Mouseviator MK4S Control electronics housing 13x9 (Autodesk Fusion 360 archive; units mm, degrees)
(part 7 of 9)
sketch "Sketch1" plane through (0, 0, 5) normal (0, 0, 1) x axis (-1, 0, 0)
  line L1 (-98.9644, -53.9879) -> (-98.9644, -59.9879)
  line L2 (-92.9644, -53.9879) -> (-98.9644, -53.9879)
  line L3 (-92.9644, -59.9879) -> (-92.9644, -53.9879)
  line L4 (-98.9644, -59.9879) -> (-92.9644, -59.9879)
  line L5 (-12.9644, 60.0121) -> (-12.9644, 66.0121)
  line L6 (-18.9644, 60.0121) -> (-12.9644, 60.0121)
  line L7 (-18.9644, 66.0121) -> (-18.9644, 60.0121)
  line L8 (-12.9644, 66.0121) -> (-18.9644, 66.0121)
  line L9 (-45.9644, -51.9879) -> (-20.9644, -51.9879)
  line L10 (-40.9644, -54.9879) -> (-45.9644, -51.9879)
  line L11 (-70.9644, -54.9879) -> (-40.9644, -54.9879)
  line L12 (-65.9644, -51.9879) -> (-70.9644, -54.9879)
  line L13 (-90.9644, -51.9879) -> (-65.9644, -51.9879)
  line L14 (-90.9644, -6.9879) -> (-90.9644, -51.9879)
  line L15 (-93.9644, -11.9879) -> (-90.9644, -6.9879)
  line L16 (-93.9644, 18.0121) -> (-93.9644, -11.9879)
  line L17 (-90.9644, 13.0121) -> (-93.9644, 18.0121)
  line L18 (-90.9644, 58.0121) -> (-90.9644, 13.0121)
  line L19 (-65.9644, 58.0121) -> (-90.9644, 58.0121)
  line L20 (-70.9644, 61.0121) -> (-65.9644, 58.0121)
  line L21 (-40.9644, 61.0121) -> (-70.9644, 61.0121)
  line L22 (-45.9644, 58.0121) -> (-40.9644, 61.0121)
  line L23 (-20.9644, 58.0121) -> (-45.9644, 58.0121)
  line L24 (-20.9644, 13.0121) -> (-20.9644, 58.0121)
  line L25 (-17.9644, 18.0121) -> (-20.9644, 13.0121)
  line L26 (-17.9644, -11.9879) -> (-17.9644, 18.0121)
  line L27 (-20.9644, -6.9879) -> (-17.9644, -11.9879)
  line L28 (-20.9644, -51.9879) -> (-20.9644, -6.9879)
  line L29 (-12.9644, -53.9879) -> (-18.9644, -53.9879)
  line L30 (-12.9644, -59.9879) -> (-12.9644, -53.9879)
  line L31 (-18.9644, -59.9879) -> (-12.9644, -59.9879)
  line L32 (-18.9644, -53.9879) -> (-18.9644, -59.9879)
  line L33 (-98.9644, 60.0121) -> (-92.9644, 60.0121)
  line L34 (-98.9644, 66.0121) -> (-98.9644, 60.0121)
  line L35 (-92.9644, 66.0121) -> (-98.9644, 66.0121)
  line L36 (-92.9644, 60.0121) -> (-92.9644, 66.0121)
  line L37 (-10.9644, -6.9879) -> (-10.9644, -61.9879)
  line L38 (-13.9644, -11.9879) -> (-10.9644, -6.9879)
  line L39 (-13.9644, 18.0121) -> (-13.9644, -11.9879)
  line L40 (-10.9644, 13.0121) -> (-13.9644, 18.0121)
  line L41 (-10.9644, 68.0121) -> (-10.9644, 13.0121)
  line L42 (-45.9644, 68.0121) -> (-10.9644, 68.0121)
  line L43 (-40.9644, 65.0121) -> (-45.9644, 68.0121)
  line L44 (-70.9644, 65.0121) -> (-40.9644, 65.0121)
  line L45 (-65.9644, 68.0121) -> (-70.9644, 65.0121)
  line L46 (-100.9644, 68.0121) -> (-65.9644, 68.0121)
  line L47 (-100.9644, 13.0121) -> (-100.9644, 68.0121)
  line L48 (-97.9644, 18.0121) -> (-100.9644, 13.0121)
  line L49 (-97.9644, -11.9879) -> (-97.9644, 18.0121)
  line L50 (-100.9644, -6.9879) -> (-97.9644, -11.9879)
  line L51 (-100.9644, -61.9879) -> (-100.9644, -6.9879)
  line L52 (-65.9644, -61.9879) -> (-100.9644, -61.9879)
  line L53 (-70.9644, -58.9879) -> (-65.9644, -61.9879)
  line L54 (-40.9644, -58.9879) -> (-70.9644, -58.9879)
  line L55 (-45.9644, -61.9879) -> (-40.9644, -58.9879)
  line L56 (-10.9644, -61.9879) -> (-45.9644, -61.9879)
  line L57 (-100.9644, -61.9879) -> (-10.9644, -61.9879)
  line L58 (-99.9644, -60.9879) -> (-100.9644, -61.9879)
  line L59 (-91.9644, -60.9879) -> (-99.9644, -60.9879)
  line L60 (-91.9644, -59.9879) -> (-91.9644, -60.9879)
  line L61 (-19.9644, -59.9879) -> (-91.9644, -59.9879)
  line L62 (-19.9644, -60.9879) -> (-19.9644, -59.9879)
  line L63 (-11.9644, -60.9879) -> (-19.9644, -60.9879)
  line L64 (-10.9644, -61.9879) -> (-11.9644, -60.9879)
  line L65 (-99.9437, -61.0379) -> (-100.8937, -61.9879)
  line L66 (-91.9144, -61.0379) -> (-99.9437, -61.0379)
  line L67 (-91.9144, -60.0379) -> (-91.9144, -61.0379)
  line L68 (-20.0144, -60.0379) -> (-91.9144, -60.0379)
  line L69 (-20.0144, -61.0379) -> (-20.0144, -60.0379)
  line L70 (-11.9851, -61.0379) -> (-20.0144, -61.0379)
  line L71 (-11.0351, -61.9879) -> (-11.9851, -61.0379)
  circle C1 centre (-24.4644, 61.5121) radius 1.7
  circle C2 centre (-93.9644, 54.5121) radius 1.7
  circle C3 centre (-87.4644, -55.4879) radius 1.7
  circle C4 centre (-17.4644, -48.4879) radius 1.7
  circle C5 centre (-24.4644, -55.4879) radius 1.7
  circle C6 centre (-93.9644, -48.4879) radius 1.7
  circle C7 centre (-87.4644, 61.5121) radius 1.7
  circle C8 centre (-17.4644, 54.5121) radius 1.7
  point P46 (-10.9644, -61.9879)
  point P74 (-10.9644, -61.9879)
  point P61 (-100.9644, -61.9879)
  point P76 (-100.9644, -61.9879)
  point P68 (-99.9644, -60.9879)
  point P77 (-99.9644, -60.9879)
  point P69 (-91.9644, -60.9879)
  point P78 (-91.9644, -60.9879)
  point P70 (-91.9644, -59.9879)
  point P79 (-91.9644, -59.9879)
  point P71 (-19.9644, -59.9879)
  point P80 (-19.9644, -59.9879)
  point P72 (-19.9644, -60.9879)
  point P81 (-19.9644, -60.9879)
  point P73 (-11.9644, -60.9879)
  point P82 (-11.9644, -60.9879)
  point P89 (-11.0351, -61.9879)
  point P90 (-100.8937, -61.9879)
  point P75 (-100.9644, -61.9879)
  coincident P46 P74
  coincident P61 P76
  coincident P68 P77
  coincident P69 P78
  coincident P70 P79
  coincident P71 P80
  coincident P72 P81
  coincident P73 P82
  coincident L56 P89
  coincident L52 P90
  dimension "d228_3_3" distance L57 L70 = 0.95 (= "side_wall_thick1")
  dimension "d229_3_3" distance L57 L68 = 1.95 (= "side_wall_thick2")
  dimension "d230_3_3" distance L57 L66 = 0.95 (= "side_wall_thick1")
  dimension "d231_3_3" distance P74 P75 = 90 (= "plate_height")
  dimension "d232_3_3" distance L64 L71 = 0.05 (= "wall_clearance")
  dimension "d233_3_3" distance L58 L65 = 0.05 (= "wall_clearance")
  dimension "d234_3_3" angle L57 L58 = 45 (= "wall_rorner_angle")
  dimension "d235_3_3" distance P74 L69 = 9.05 (= "side_wall_col_length")
  dimension "d244_3_3" distance P75 L67 = 9.05 (= "side_wall_col_length")
extrude "Extrude1" new body sketch "Sketch1" profile of L52 L53 L55 L56 blind 69.9 (= "column_height - ( 2 * wall_clearance )") named "d217_3_3" from offset 0.05 (= "wall_clearance") named "d216_3_3"
sketch "Sketch2" plane through (0, 61.9879, 0) normal (0, 1, 0) x axis (-1, 0, 0)
  line L1 (-11.0351, 74.95) -> (-100.8937, 74.95)
  line L2 (-100.8937, 74.95) -> (-100.8937, 5.05)
  line L3 (-11.0351, 74.95) -> (-11.0351, 5.05)
  line L4 (-11.0351, 5.05) -> (-100.8937, 5.05)
  line L5 (-11.0351, 74.95) -> (-11.0351, 5.05)
  line L6 (-100.8937, 74.95) -> (-11.0351, 74.95)
  line L7 (-100.8937, 5.05) -> (-100.8937, 74.95)
  line L8 (-90.8937, 64.95) -> (-21.0351, 64.95)
  line L9 (-90.8937, 15.05) -> (-90.8937, 64.95)
  line L10 (-21.0351, 15.05) -> (-90.8937, 15.05)
  line L11 (-21.0351, 64.95) -> (-21.0351, 15.05)
  circle C1 centre (-95.9644, 60) radius 1.7
  circle C2 centre (-95.9644, 20) radius 1.7
  circle C3 centre (-15.9644, 20) radius 1.7
  circle C4 centre (-15.9644, 60) radius 1.7
hole "Hole1" HoleDepth 4 named "d220_3_3" HoleDiameter 3.4 named "d221_3_3" TipAngle 118 named "d222_3_3"
sketch "Sketch3" plane through (0, 61.9879, 0) normal (0, 1, 0) x axis (-1, 0, 0)
  line L1 (-11.0351, 5.05) -> (-100.8937, 5.05)
  line L2 (-11.0351, 74.95) -> (-11.0351, 5.05)
  line L3 (-100.8937, 74.95) -> (-11.0351, 74.95)
  line L4 (-100.8937, 5.05) -> (-100.8937, 74.95)
  line L5 (-55.9644, -6.6527) -> (-55.9644, 156.5527)
  line L6 (83.5909, 40) -> (-105.6612, 40)
  line L7 (-100.8937, 64.95) -> (-100.8937, 74.95)
  line L8 (-94.8937, 74.95) -> (-100.8937, 74.95)
  line L9 (-94.8937, 59.95) -> (-94.8937, 74.95)
  line L10 (-100.8937, 64.95) -> (-94.8937, 59.95)
  line L11 (-100.9437, 64.9735) -> (-106.8437, 60)
  line L12 (-106.8437, 60) -> (-106.8437, 74.9)
  line L13 (-100.8937, 64.9735) -> (-100.9437, 64.9735)
  line L14 (-100.8937, 74.9) -> (-106.8437, 74.9)
  line L15 (-100.8937, 5.1) -> (-106.8437, 5.1)
  line L16 (-106.8437, 20) -> (-106.8437, 5.1)
  line L17 (-100.9437, 15.0265) -> (-106.8437, 20)
  line L18 (-100.8937, 15.0265) -> (-100.9437, 15.0265)
  line L19 (-100.8937, 15.05) -> (-100.8937, 5.05)
  line L20 (-94.8937, 5.05) -> (-100.8937, 5.05)
  line L21 (-94.8937, 20.05) -> (-94.8937, 5.05)
  line L22 (-100.8937, 15.05) -> (-94.8937, 20.05)
  line L23 (-11.0351, 5.1) -> (-5.0851, 5.1)
  line L24 (-5.0851, 20) -> (-5.0851, 5.1)
  line L25 (-10.9851, 15.0265) -> (-5.0851, 20)
  line L26 (-11.0351, 15.0265) -> (-10.9851, 15.0265)
  line L27 (-11.0351, 15.05) -> (-11.0351, 5.05)
  line L28 (-17.0351, 5.05) -> (-11.0351, 5.05)
  line L29 (-17.0351, 20.05) -> (-17.0351, 5.05)
  line L30 (-11.0351, 15.05) -> (-17.0351, 20.05)
  line L31 (-11.0351, 74.9) -> (-5.0851, 74.9)
  line L32 (-5.0851, 60) -> (-5.0851, 74.9)
  line L33 (-11.0351, 64.9735) -> (-10.9851, 64.9735)
  line L34 (-10.9851, 64.9735) -> (-5.0851, 60)
  line L35 (-11.0351, 64.95) -> (-11.0351, 74.95)
  line L36 (-17.0351, 74.95) -> (-11.0351, 74.95)
  line L37 (-17.0351, 59.95) -> (-17.0351, 74.95)
  line L38 (-11.0351, 64.95) -> (-17.0351, 59.95)
  point P17 (-100.8937, 64.9735)
  point P18 (-100.8937, 74.9)
  point P10 (-100.8937, 74.95)
  point P24 (-100.8937, 5.05)
  point P11 (-100.8937, 64.95)
  point P25 (-100.8937, 15.05)
  point P12 (-94.8937, 74.95)
  point P26 (-94.8937, 5.05)
  point P13 (-94.8937, 59.95)
  point P27 (-94.8937, 20.05)
  point P14 (-100.9437, 64.9735)
  point P22 (-100.9437, 15.0265)
  point P15 (-106.8437, 60)
  point P21 (-106.8437, 20)
  point P16 (-106.8437, 74.9)
  point P19 (-106.8437, 5.1)
  point P23 (-100.8937, 15.0265)
  point P20 (-100.8937, 5.1)
  point P42 (-11.0351, 74.95)
  point P43 (-11.0351, 64.95)
  point P44 (-17.0351, 74.95)
  point P45 (-17.0351, 59.95)
  point P40 (-10.9851, 64.9735)
  point P39 (-5.0851, 60)
  point P37 (-5.0851, 74.9)
  point P41 (-11.0351, 64.9735)
  point P38 (-11.0351, 74.9)
  point P28 (-5.0851, 5.1)
  point P29 (-11.0351, 5.1)
  point P30 (-5.0851, 20)
  point P31 (-10.9851, 15.0265)
  point P32 (-11.0351, 15.0265)
  point P33 (-11.0351, 5.05)
  point P34 (-11.0351, 15.05)
  point P35 (-17.0351, 5.05)
  point P36 (-17.0351, 20.05)
  vertical L5
  horizontal L6
  midpoint L3 L5
  midpoint L2 L6
  coincident L7 P17
  coincident L4 P17
  perpendicular L7 L14
  coincident L4 P18
  symmetric L6 P10 P24
  symmetric L6 P11 P25
  symmetric L6 P12 P26
  symmetric L6 P13 P27
  symmetric L6 P14 P22
  symmetric L6 P15 P21
  symmetric L6 P16 P19
  symmetric L6 P17 P23
  symmetric L6 P18 P20
  symmetric L5 P10 P42
  symmetric L5 P11 P43
  symmetric L5 P12 P44
  symmetric L5 P13 P45
  symmetric L5 P14 P40
  symmetric L5 P15 P39
  symmetric L5 P16 P37
  symmetric L5 P17 P41
  symmetric L5 P18 P38
  symmetric L5 P19 P28
  symmetric L5 P20 P29
  symmetric L5 P21 P30
  symmetric L5 P22 P31
  symmetric L5 P23 P32
  symmetric L5 P24 P33
  symmetric L5 P25 P34
  symmetric L5 P26 P35
  symmetric L5 P27 P36
  dimension "d332_3_3" distance P12 P13 = 15 (= "join_width2")
  dimension "d333_3_3" distance P10 P12 = 6 (= "join_depth * 2")
  dimension "d334_3_3" distance P10 P11 = 10 (= "join_width1")
  dimension "d336_3_3" distance P15 P16 = 14.9 (= "join_width2 - ( 2 * wall_clearance )")
  dimension "d337_3_3" distance P16 P18 = 5.95 (= "join_depth * 2 - wall_clearance")
  dimension "d338_3_3" distance P14 P17 = 0.05 (= "wall_clearance")
position "Position26"
extrude "Extrude3" add sketch "Sketch3" profile of L1 L3 L4 L7 L8 L9 L10 L12 L11 L13 L14 L15 L16 L17 L18 L19 L20 L21 L22 against normal blind 0.95 named "d343_2" (magnitude of "-side_wall_thick1")
sketch "Sketch4" plane through (0, 61.9879, 0) normal (0, 1, 0) x axis (1, 0, 0)
  line L1 (11.0351, -5.05) -> (100.8937, -5.05)
  line L2 (11.0351, -74.95) -> (11.0351, -5.05)
  line L3 (100.8937, -74.95) -> (11.0351, -74.95)
  line L4 (100.8937, -5.05) -> (100.8937, -74.95)
  line L5 (36.6374, -5.05) -> (36.6374, -12.415)
  line L6 (26.6374, -5.05) -> (26.6374, -12.415)
  circle C1 centre (15.9644, -20) radius 1.7
  circle C2 centre (95.9644, -60) radius 1.7
  circle C3 centre (95.9644, -20) radius 1.7
  circle C4 centre (15.9644, -60) radius 1.7
  arc A1 centre (31.6374, -12.415) radius 5 clockwise from (36.6374, -12.415) to (26.6374, -12.415)
  point P12 (36.6374, -5.05)
  point P14 (26.6374, -5.05)
  coincident L1 P12
  tangent L5 A1
  coincident L1 P14
  tangent L6 A1
  perpendicular L1 L6
  dimension "cable_hole_d_3" diameter A1 = 10
extrude "Extrude4" cut sketch "Sketch4" profile of A1 L1 L5 L6 against normal blind 2 named "d517_1"
sketch "Sketch1" plane through (0, 0, 5) normal (0, 0, 1) x axis (-1, 0, 0)
  line L1 (-98.9644, -53.9879) -> (-98.9644, -59.9879)
  line L2 (-92.9644, -53.9879) -> (-98.9644, -53.9879)
  line L3 (-92.9644, -59.9879) -> (-92.9644, -53.9879)
  line L4 (-98.9644, -59.9879) -> (-92.9644, -59.9879)
  line L5 (-12.9644, 60.0121) -> (-12.9644, 66.0121)
  line L6 (-18.9644, 60.0121) -> (-12.9644, 60.0121)
  line L7 (-18.9644, 66.0121) -> (-18.9644, 60.0121)
  line L8 (-12.9644, 66.0121) -> (-18.9644, 66.0121)
  line L9 (-45.9644, -51.9879) -> (-20.9644, -51.9879)
  line L10 (-40.9644, -54.9879) -> (-45.9644, -51.9879)
  line L11 (-70.9644, -54.9879) -> (-40.9644, -54.9879)
  line L12 (-65.9644, -51.9879) -> (-70.9644, -54.9879)
  line L13 (-90.9644, -51.9879) -> (-65.9644, -51.9879)
  line L14 (-90.9644, -6.9879) -> (-90.9644, -51.9879)
  line L15 (-93.9644, -11.9879) -> (-90.9644, -6.9879)
  line L16 (-93.9644, 18.0121) -> (-93.9644, -11.9879)
  line L17 (-90.9644, 13.0121) -> (-93.9644, 18.0121)
  line L18 (-90.9644, 58.0121) -> (-90.9644, 13.0121)
  line L19 (-65.9644, 58.0121) -> (-90.9644, 58.0121)
  line L20 (-70.9644, 61.0121) -> (-65.9644, 58.0121)
  line L21 (-40.9644, 61.0121) -> (-70.9644, 61.0121)
  line L22 (-45.9644, 58.0121) -> (-40.9644, 61.0121)
  line L23 (-20.9644, 58.0121) -> (-45.9644, 58.0121)
  line L24 (-20.9644, 13.0121) -> (-20.9644, 58.0121)
  line L25 (-17.9644, 18.0121) -> (-20.9644, 13.0121)
  line L26 (-17.9644, -11.9879) -> (-17.9644, 18.0121)
  line L27 (-20.9644, -6.9879) -> (-17.9644, -11.9879)
  line L28 (-20.9644, -51.9879) -> (-20.9644, -6.9879)
  line L29 (-12.9644, -53.9879) -> (-18.9644, -53.9879)
  line L30 (-12.9644, -59.9879) -> (-12.9644, -53.9879)
  line L31 (-18.9644, -59.9879) -> (-12.9644, -59.9879)
  line L32 (-18.9644, -53.9879) -> (-18.9644, -59.9879)
  line L33 (-98.9644, 60.0121) -> (-92.9644, 60.0121)
  line L34 (-98.9644, 66.0121) -> (-98.9644, 60.0121)
  line L35 (-92.9644, 66.0121) -> (-98.9644, 66.0121)
  line L36 (-92.9644, 60.0121) -> (-92.9644, 66.0121)
  line L37 (-10.9644, -6.9879) -> (-10.9644, -61.9879)
  line L38 (-13.9644, -11.9879) -> (-10.9644, -6.9879)
  line L39 (-13.9644, 18.0121) -> (-13.9644, -11.9879)
  line L40 (-10.9644, 13.0121) -> (-13.9644, 18.0121)
  line L41 (-10.9644, 68.0121) -> (-10.9644, 13.0121)
  line L42 (-45.9644, 68.0121) -> (-10.9644, 68.0121)
  line L43 (-40.9644, 65.0121) -> (-45.9644, 68.0121)
  line L44 (-70.9644, 65.0121) -> (-40.9644, 65.0121)
  line L45 (-65.9644, 68.0121) -> (-70.9644, 65.0121)
  line L46 (-100.9644, 68.0121) -> (-65.9644, 68.0121)
  line L47 (-100.9644, 13.0121) -> (-100.9644, 68.0121)
  line L48 (-97.9644, 18.0121) -> (-100.9644, 13.0121)
  line L49 (-97.9644, -11.9879) -> (-97.9644, 18.0121)
  line L50 (-100.9644, -6.9879) -> (-97.9644, -11.9879)
  line L51 (-100.9644, -61.9879) -> (-100.9644, -6.9879)
  line L52 (-65.9644, -61.9879) -> (-100.9644, -61.9879)
  line L53 (-70.9644, -58.9879) -> (-65.9644, -61.9879)
  line L54 (-40.9644, -58.9879) -> (-70.9644, -58.9879)
  line L55 (-45.9644, -61.9879) -> (-40.9644, -58.9879)
  line L56 (-10.9644, -61.9879) -> (-45.9644, -61.9879)
  line L57 (-100.9644, -61.9879) -> (-10.9644, -61.9879)
  line L58 (-99.9644, -60.9879) -> (-100.9644, -61.9879)
  line L59 (-91.9644, -60.9879) -> (-99.9644, -60.9879)
  line L60 (-91.9644, -59.9879) -> (-91.9644, -60.9879)
  line L61 (-19.9644, -59.9879) -> (-91.9644, -59.9879)
  line L62 (-19.9644, -60.9879) -> (-19.9644, -59.9879)
  line L63 (-11.9644, -60.9879) -> (-19.9644, -60.9879)
  line L64 (-10.9644, -61.9879) -> (-11.9644, -60.9879)
  line L65 (-99.9437, -61.0379) -> (-100.8937, -61.9879)
  line L66 (-91.9144, -61.0379) -> (-99.9437, -61.0379)
  line L67 (-91.9144, -60.0379) -> (-91.9144, -61.0379)
  line L68 (-20.0144, -60.0379) -> (-91.9144, -60.0379)
  line L69 (-20.0144, -61.0379) -> (-20.0144, -60.0379)
  line L70 (-11.9851, -61.0379) -> (-20.0144, -61.0379)
  line L71 (-11.0351, -61.9879) -> (-11.9851, -61.0379)
  circle C1 centre (-24.4644, 61.5121) radius 1.7
  circle C2 centre (-93.9644, 54.5121) radius 1.7
  circle C3 centre (-87.4644, -55.4879) radius 1.7
  circle C4 centre (-17.4644, -48.4879) radius 1.7
  circle C5 centre (-24.4644, -55.4879) radius 1.7
  circle C6 centre (-93.9644, -48.4879) radius 1.7
  circle C7 centre (-87.4644, 61.5121) radius 1.7
  circle C8 centre (-17.4644, 54.5121) radius 1.7
  point P46 (-10.9644, -61.9879)
  point P74 (-10.9644, -61.9879)
  point P61 (-100.9644, -61.9879)
  point P76 (-100.9644, -61.9879)
  point P68 (-99.9644, -60.9879)
  point P77 (-99.9644, -60.9879)
  point P69 (-91.9644, -60.9879)
  point P78 (-91.9644, -60.9879)
  point P70 (-91.9644, -59.9879)
  point P79 (-91.9644, -59.9879)
  point P71 (-19.9644, -59.9879)
  point P80 (-19.9644, -59.9879)
  point P72 (-19.9644, -60.9879)
  point P81 (-19.9644, -60.9879)
  point P73 (-11.9644, -60.9879)
  point P82 (-11.9644, -60.9879)
  point P89 (-11.0351, -61.9879)
  point P90 (-100.8937, -61.9879)
  point P75 (-100.9644, -61.9879)
  coincident P46 P74
  coincident P61 P76
  coincident P68 P77
  coincident P69 P78
  coincident P70 P79
  coincident P71 P80
  coincident P72 P81
  coincident P73 P82
  coincident L56 P89
  coincident L52 P90
  dimension "d228_2_1" distance L57 L70 = 0.95 (= "side_wall_thick1")
  dimension "d229_2_1" distance L57 L68 = 1.95 (= "side_wall_thick2")
  dimension "d230_2_1" distance L57 L66 = 0.95 (= "side_wall_thick1")
  dimension "d231_2_1" distance P74 P75 = 90 (= "plate_height")
  dimension "d232_2_1" distance L64 L71 = 0.05 (= "wall_clearance")
  dimension "d233_2_1" distance L58 L65 = 0.05 (= "wall_clearance")
  dimension "d234_2_1" angle L57 L58 = 45 (= "wall_rorner_angle")
  dimension "d235_2_1" distance P74 L69 = 9.05 (= "side_wall_col_length")
  dimension "d244_2_1" distance P75 L67 = 9.05 (= "side_wall_col_length")
extrude "Extrude1" new body sketch "Sketch1" profile of L52 L53 L55 L56 blind 69.9 (= "column_height - ( 2 * wall_clearance )") named "d217_2_1" from offset 0.05 (= "wall_clearance") named "d216_2_1"
sketch "Sketch2" plane through (0, 61.9879, 0) normal (0, 1, 0) x axis (-1, 0, 0)
  line L1 (-11.0351, 74.95) -> (-100.8937, 74.95)
  line L2 (-100.8937, 74.95) -> (-100.8937, 5.05)
  line L3 (-11.0351, 74.95) -> (-11.0351, 5.05)
  line L4 (-11.0351, 5.05) -> (-100.8937, 5.05)
  line L5 (-11.0351, 74.95) -> (-11.0351, 5.05)
  line L6 (-100.8937, 74.95) -> (-11.0351, 74.95)
  line L7 (-100.8937, 5.05) -> (-100.8937, 74.95)
  line L8 (-90.8937, 64.95) -> (-21.0351, 64.95)
  line L9 (-90.8937, 15.05) -> (-90.8937, 64.95)
  line L10 (-21.0351, 15.05) -> (-90.8937, 15.05)
  line L11 (-21.0351, 64.95) -> (-21.0351, 15.05)
  circle C1 centre (-95.9644, 60) radius 1.7
  circle C2 centre (-95.9644, 20) radius 1.7
  circle C3 centre (-15.9644, 20) radius 1.7
  circle C4 centre (-15.9644, 60) radius 1.7
hole "Hole1" HoleDepth 4 named "d220_2_1" HoleDiameter 3.4 named "d221_2_1" TipAngle 118 named "d222_2_1"
sketch "Sketch3" plane through (0, 61.9879, 0) normal (0, 1, 0) x axis (-1, 0, 0)
  line L1 (-11.0351, 5.05) -> (-100.8937, 5.05)
  line L2 (-11.0351, 74.95) -> (-11.0351, 5.05)
  line L3 (-100.8937, 74.95) -> (-11.0351, 74.95)
  line L4 (-100.8937, 5.05) -> (-100.8937, 74.95)
  line L5 (-55.9644, -6.6527) -> (-55.9644, 156.5527)
  line L6 (83.5909, 40) -> (-105.6612, 40)
  line L7 (-100.8937, 64.95) -> (-100.8937, 74.95)
  line L8 (-94.8937, 74.95) -> (-100.8937, 74.95)
  line L9 (-94.8937, 59.95) -> (-94.8937, 74.95)
  line L10 (-100.8937, 64.95) -> (-94.8937, 59.95)
  line L11 (-100.9437, 64.9735) -> (-106.8437, 60)
  line L12 (-106.8437, 60) -> (-106.8437, 74.9)
  line L13 (-100.8937, 64.9735) -> (-100.9437, 64.9735)
  line L14 (-100.8937, 74.9) -> (-106.8437, 74.9)
  line L15 (-100.8937, 5.1) -> (-106.8437, 5.1)
  line L16 (-106.8437, 20) -> (-106.8437, 5.1)
  line L17 (-100.9437, 15.0265) -> (-106.8437, 20)
  line L18 (-100.8937, 15.0265) -> (-100.9437, 15.0265)
  line L19 (-100.8937, 15.05) -> (-100.8937, 5.05)
  line L20 (-94.8937, 5.05) -> (-100.8937, 5.05)
  line L21 (-94.8937, 20.05) -> (-94.8937, 5.05)
  line L22 (-100.8937, 15.05) -> (-94.8937, 20.05)
  line L23 (-11.0351, 5.1) -> (-5.0851, 5.1)
  line L24 (-5.0851, 20) -> (-5.0851, 5.1)
  line L25 (-10.9851, 15.0265) -> (-5.0851, 20)
  line L26 (-11.0351, 15.0265) -> (-10.9851, 15.0265)
  line L27 (-11.0351, 15.05) -> (-11.0351, 5.05)
  line L28 (-17.0351, 5.05) -> (-11.0351, 5.05)
  line L29 (-17.0351, 20.05) -> (-17.0351, 5.05)
  line L30 (-11.0351, 15.05) -> (-17.0351, 20.05)
  line L31 (-11.0351, 74.9) -> (-5.0851, 74.9)
  line L32 (-5.0851, 60) -> (-5.0851, 74.9)
  line L33 (-11.0351, 64.9735) -> (-10.9851, 64.9735)
  line L34 (-10.9851, 64.9735) -> (-5.0851, 60)
  line L35 (-11.0351, 64.95) -> (-11.0351, 74.95)
  line L36 (-17.0351, 74.95) -> (-11.0351, 74.95)
  line L37 (-17.0351, 59.95) -> (-17.0351, 74.95)
  line L38 (-11.0351, 64.95) -> (-17.0351, 59.95)
  point P17 (-100.8937, 64.9735)
  point P18 (-100.8937, 74.9)
  point P10 (-100.8937, 74.95)
  point P24 (-100.8937, 5.05)
  point P11 (-100.8937, 64.95)
  point P25 (-100.8937, 15.05)
  point P12 (-94.8937, 74.95)
  point P26 (-94.8937, 5.05)
  point P13 (-94.8937, 59.95)
  point P27 (-94.8937, 20.05)
  point P14 (-100.9437, 64.9735)
  point P22 (-100.9437, 15.0265)
  point P15 (-106.8437, 60)
  point P21 (-106.8437, 20)
  point P16 (-106.8437, 74.9)
  point P19 (-106.8437, 5.1)
  point P23 (-100.8937, 15.0265)
  point P20 (-100.8937, 5.1)
  point P42 (-11.0351, 74.95)
  point P43 (-11.0351, 64.95)
  point P44 (-17.0351, 74.95)
  point P45 (-17.0351, 59.95)
  point P40 (-10.9851, 64.9735)
  point P39 (-5.0851, 60)
  point P37 (-5.0851, 74.9)
  point P41 (-11.0351, 64.9735)
  point P38 (-11.0351, 74.9)
  point P28 (-5.0851, 5.1)
  point P29 (-11.0351, 5.1)
  point P30 (-5.0851, 20)
  point P31 (-10.9851, 15.0265)
  point P32 (-11.0351, 15.0265)
  point P33 (-11.0351, 5.05)
  point P34 (-11.0351, 15.05)
  point P35 (-17.0351, 5.05)
  point P36 (-17.0351, 20.05)
  vertical L5
  horizontal L6
  midpoint L3 L5
  midpoint L2 L6
  coincident L7 P17
  coincident L4 P17
  perpendicular L7 L14
  coincident L4 P18
  symmetric L6 P10 P24
  symmetric L6 P11 P25
  symmetric L6 P12 P26
  symmetric L6 P13 P27
  symmetric L6 P14 P22
  symmetric L6 P15 P21
  symmetric L6 P16 P19
  symmetric L6 P17 P23
  symmetric L6 P18 P20
  symmetric L5 P10 P42
  symmetric L5 P11 P43
  symmetric L5 P12 P44
  symmetric L5 P13 P45
  symmetric L5 P14 P40
  symmetric L5 P15 P39
  symmetric L5 P16 P37
  symmetric L5 P17 P41
  symmetric L5 P18 P38
  symmetric L5 P19 P28
  symmetric L5 P20 P29
  symmetric L5 P21 P30
  symmetric L5 P22 P31
  symmetric L5 P23 P32
  symmetric L5 P24 P33
  symmetric L5 P25 P34
  symmetric L5 P26 P35
  symmetric L5 P27 P36
  dimension "d332_2_1" distance P12 P13 = 15 (= "join_width2")
  dimension "d333_2_1" distance P10 P12 = 6 (= "join_depth * 2")
  dimension "d334_2_1" distance P10 P11 = 10 (= "join_width1")
  dimension "d336_2_1" distance P15 P16 = 14.9 (= "join_width2 - ( 2 * wall_clearance )")
  dimension "d337_2_1" distance P16 P18 = 5.95 (= "join_depth * 2 - wall_clearance")
  dimension "d338_2_1" distance P14 P17 = 0.05 (= "wall_clearance")
position "Position27"
extrude "Extrude3" cut sketch "Sketch3" profile of L1 L3 L4 L7 L8 L9 L10 L19 L20 L21 L22 against normal blind 2 named "d341_1"
sketch "Sketch1" plane through (0, 0, 5) normal (0, 0, 1) x axis (-1, 0, 0)
  line L1 (-98.9644, -53.9879) -> (-98.9644, -59.9879)
  line L2 (-92.9644, -53.9879) -> (-98.9644, -53.9879)
  line L3 (-92.9644, -59.9879) -> (-92.9644, -53.9879)
  line L4 (-98.9644, -59.9879) -> (-92.9644, -59.9879)
  line L5 (-12.9644, 60.0121) -> (-12.9644, 66.0121)
  line L6 (-18.9644, 60.0121) -> (-12.9644, 60.0121)
  line L7 (-18.9644, 66.0121) -> (-18.9644, 60.0121)
  line L8 (-12.9644, 66.0121) -> (-18.9644, 66.0121)
  line L9 (-45.9644, -51.9879) -> (-20.9644, -51.9879)
  line L10 (-40.9644, -54.9879) -> (-45.9644, -51.9879)
  line L11 (-70.9644, -54.9879) -> (-40.9644, -54.9879)
  line L12 (-65.9644, -51.9879) -> (-70.9644, -54.9879)
  line L13 (-90.9644, -51.9879) -> (-65.9644, -51.9879)
  line L14 (-90.9644, -6.9879) -> (-90.9644, -51.9879)
  line L15 (-93.9644, -11.9879) -> (-90.9644, -6.9879)
  line L16 (-93.9644, 18.0121) -> (-93.9644, -11.9879)
  line L17 (-90.9644, 13.0121) -> (-93.9644, 18.0121)
  line L18 (-90.9644, 58.0121) -> (-90.9644, 13.0121)
  line L19 (-65.9644, 58.0121) -> (-90.9644, 58.0121)
  line L20 (-70.9644, 61.0121) -> (-65.9644, 58.0121)
  line L21 (-40.9644, 61.0121) -> (-70.9644, 61.0121)
  line L22 (-45.9644, 58.0121) -> (-40.9644, 61.0121)
  line L23 (-20.9644, 58.0121) -> (-45.9644, 58.0121)
  line L24 (-20.9644, 13.0121) -> (-20.9644, 58.0121)
  line L25 (-17.9644, 18.0121) -> (-20.9644, 13.0121)
  line L26 (-17.9644, -11.9879) -> (-17.9644, 18.0121)
  line L27 (-20.9644, -6.9879) -> (-17.9644, -11.9879)
  line L28 (-20.9644, -51.9879) -> (-20.9644, -6.9879)
  line L29 (-12.9644, -53.9879) -> (-18.9644, -53.9879)
  line L30 (-12.9644, -59.9879) -> (-12.9644, -53.9879)
  line L31 (-18.9644, -59.9879) -> (-12.9644, -59.9879)
  line L32 (-18.9644, -53.9879) -> (-18.9644, -59.9879)
  line L33 (-98.9644, 60.0121) -> (-92.9644, 60.0121)
  line L34 (-98.9644, 66.0121) -> (-98.9644, 60.0121)
  line L35 (-92.9644, 66.0121) -> (-98.9644, 66.0121)
  line L36 (-92.9644, 60.0121) -> (-92.9644, 66.0121)
  line L37 (-10.9644, -6.9879) -> (-10.9644, -61.9879)
  line L38 (-13.9644, -11.9879) -> (-10.9644, -6.9879)
  line L39 (-13.9644, 18.0121) -> (-13.9644, -11.9879)
  line L40 (-10.9644, 13.0121) -> (-13.9644, 18.0121)
  line L41 (-10.9644, 68.0121) -> (-10.9644, 13.0121)
  line L42 (-45.9644, 68.0121) -> (-10.9644, 68.0121)
  line L43 (-40.9644, 65.0121) -> (-45.9644, 68.0121)
  line L44 (-70.9644, 65.0121) -> (-40.9644, 65.0121)
  line L45 (-65.9644, 68.0121) -> (-70.9644, 65.0121)
  line L46 (-100.9644, 68.0121) -> (-65.9644, 68.0121)
  line L47 (-100.9644, 13.0121) -> (-100.9644, 68.0121)
  line L48 (-97.9644, 18.0121) -> (-100.9644, 13.0121)
  line L49 (-97.9644, -11.9879) -> (-97.9644, 18.0121)
  line L50 (-100.9644, -6.9879) -> (-97.9644, -11.9879)
  line L51 (-100.9644, -61.9879) -> (-100.9644, -6.9879)
  line L52 (-65.9644, -61.9879) -> (-100.9644, -61.9879)
  line L53 (-70.9644, -58.9879) -> (-65.9644, -61.9879)
  line L54 (-40.9644, -58.9879) -> (-70.9644, -58.9879)
  line L55 (-45.9644, -61.9879) -> (-40.9644, -58.9879)
  line L56 (-10.9644, -61.9879) -> (-45.9644, -61.9879)
  line L57 (-100.9644, -61.9879) -> (-10.9644, -61.9879)
  line L58 (-99.9644, -60.9879) -> (-100.9644, -61.9879)
  line L59 (-91.9644, -60.9879) -> (-99.9644, -60.9879)
  line L60 (-91.9644, -59.9879) -> (-91.9644, -60.9879)
  line L61 (-19.9644, -59.9879) -> (-91.9644, -59.9879)
  line L62 (-19.9644, -60.9879) -> (-19.9644, -59.9879)
  line L63 (-11.9644, -60.9879) -> (-19.9644, -60.9879)
  line L64 (-10.9644, -61.9879) -> (-11.9644, -60.9879)
  line L65 (-99.9437, -61.0379) -> (-100.8937, -61.9879)
  line L66 (-91.9144, -61.0379) -> (-99.9437, -61.0379)
  line L67 (-91.9144, -60.0379) -> (-91.9144, -61.0379)
  line L68 (-20.0144, -60.0379) -> (-91.9144, -60.0379)
  line L69 (-20.0144, -61.0379) -> (-20.0144, -60.0379)
  line L70 (-11.9851, -61.0379) -> (-20.0144, -61.0379)
  line L71 (-11.0351, -61.9879) -> (-11.9851, -61.0379)
  circle C1 centre (-24.4644, 61.5121) radius 1.7
  circle C2 centre (-93.9644, 54.5121) radius 1.7
  circle C3 centre (-87.4644, -55.4879) radius 1.7
  circle C4 centre (-17.4644, -48.4879) radius 1.7
  circle C5 centre (-24.4644, -55.4879) radius 1.7
  circle C6 centre (-93.9644, -48.4879) radius 1.7
  circle C7 centre (-87.4644, 61.5121) radius 1.7
  circle C8 centre (-17.4644, 54.5121) radius 1.7
  point P46 (-10.9644, -61.9879)
  point P74 (-10.9644, -61.9879)
  point P61 (-100.9644, -61.9879)
  point P76 (-100.9644, -61.9879)
  point P68 (-99.9644, -60.9879)
  point P77 (-99.9644, -60.9879)
  point P69 (-91.9644, -60.9879)
  point P78 (-91.9644, -60.9879)
  point P70 (-91.9644, -59.9879)
  point P79 (-91.9644, -59.9879)
  point P71 (-19.9644, -59.9879)
  point P80 (-19.9644, -59.9879)
  point P72 (-19.9644, -60.9879)
  point P81 (-19.9644, -60.9879)
  point P73 (-11.9644, -60.9879)
  point P82 (-11.9644, -60.9879)
  point P89 (-11.0351, -61.9879)
  point P90 (-100.8937, -61.9879)
  point P75 (-100.9644, -61.9879)
  coincident P46 P74
  coincident P61 P76
  coincident P68 P77
  coincident P69 P78
  coincident P70 P79
  coincident P71 P80
  coincident P72 P81
  coincident P73 P82
  coincident L56 P89
  coincident L52 P90
  dimension "d228_3_1_1" distance L57 L70 = 0.95 (= "side_wall_thick1")
  dimension "d229_3_1_1" distance L57 L68 = 1.95 (= "side_wall_thick2")
  dimension "d230_3_1_1" distance L57 L66 = 0.95 (= "side_wall_thick1")
  dimension "d231_3_1_1" distance P74 P75 = 90 (= "plate_height")
  dimension "d232_3_1_1" distance L64 L71 = 0.05 (= "wall_clearance")
  dimension "d233_3_1_1" distance L58 L65 = 0.05 (= "wall_clearance")
  dimension "d234_3_1_1" angle L57 L58 = 45 (= "wall_rorner_angle")
  dimension "d235_3_1_1" distance P74 L69 = 9.05 (= "side_wall_col_length")
  dimension "d244_3_1_1" distance P75 L67 = 9.05 (= "side_wall_col_length")
extrude "Extrude1" new body sketch "Sketch1" profile of L52 L53 L55 L56 blind 69.9 (= "column_height - ( 2 * wall_clearance )") named "d217_3_1_1" from offset 0.05 (= "wall_clearance") named "d216_3_1_1"
sketch "Sketch2" plane through (0, 61.9879, 0) normal (0, 1, 0) x axis (-1, 0, 0)
  line L1 (-11.0351, 74.95) -> (-100.8937, 74.95)
  line L2 (-100.8937, 74.95) -> (-100.8937, 5.05)
  line L3 (-11.0351, 74.95) -> (-11.0351, 5.05)
  line L4 (-11.0351, 5.05) -> (-100.8937, 5.05)
  line L5 (-11.0351, 74.95) -> (-11.0351, 5.05)
  line L6 (-100.8937, 74.95) -> (-11.0351, 74.95)
  line L7 (-100.8937, 5.05) -> (-100.8937, 74.95)
  line L8 (-90.8937, 64.95) -> (-21.0351, 64.95)
  line L9 (-90.8937, 15.05) -> (-90.8937, 64.95)
  line L10 (-21.0351, 15.05) -> (-90.8937, 15.05)
  line L11 (-21.0351, 64.95) -> (-21.0351, 15.05)
  circle C1 centre (-95.9644, 60) radius 1.7
  circle C2 centre (-95.9644, 20) radius 1.7
  circle C3 centre (-15.9644, 20) radius 1.7
  circle C4 centre (-15.9644, 60) radius 1.7
hole "Hole1" HoleDepth 4 named "d220_3_1_1" HoleDiameter 3.4 named "d221_3_1_1" TipAngle 118 named "d222_3_1_1"
sketch "Sketch3" plane through (0, 61.9879, 0) normal (0, 1, 0) x axis (-1, 0, 0)
  line L1 (-11.0351, 5.05) -> (-100.8937, 5.05)
  line L2 (-11.0351, 74.95) -> (-11.0351, 5.05)
  line L3 (-100.8937, 74.95) -> (-11.0351, 74.95)
  line L4 (-100.8937, 5.05) -> (-100.8937, 74.95)
  line L5 (-55.9644, -6.6527) -> (-55.9644, 156.5527)
  line L6 (83.5909, 40) -> (-105.6612, 40)
  line L7 (-100.8937, 64.95) -> (-100.8937, 74.95)
  line L8 (-94.8937, 74.95) -> (-100.8937, 74.95)
  line L9 (-94.8937, 59.95) -> (-94.8937, 74.95)
  line L10 (-100.8937, 64.95) -> (-94.8937, 59.95)
  line L11 (-100.9437, 64.9735) -> (-106.8437, 60)
  line L12 (-106.8437, 60) -> (-106.8437, 74.9)
  line L13 (-100.8937, 64.9735) -> (-100.9437, 64.9735)
  line L14 (-100.8937, 74.9) -> (-106.8437, 74.9)
  line L15 (-100.8937, 5.1) -> (-106.8437, 5.1)
  line L16 (-106.8437, 20) -> (-106.8437, 5.1)
  line L17 (-100.9437, 15.0265) -> (-106.8437, 20)
  line L18 (-100.8937, 15.0265) -> (-100.9437, 15.0265)
  line L19 (-100.8937, 15.05) -> (-100.8937, 5.05)
  line L20 (-94.8937, 5.05) -> (-100.8937, 5.05)
  line L21 (-94.8937, 20.05) -> (-94.8937, 5.05)
  line L22 (-100.8937, 15.05) -> (-94.8937, 20.05)
  line L23 (-11.0351, 5.1) -> (-5.0851, 5.1)
  line L24 (-5.0851, 20) -> (-5.0851, 5.1)
  line L25 (-10.9851, 15.0265) -> (-5.0851, 20)
  line L26 (-11.0351, 15.0265) -> (-10.9851, 15.0265)
  line L27 (-11.0351, 15.05) -> (-11.0351, 5.05)
  line L28 (-17.0351, 5.05) -> (-11.0351, 5.05)
  line L29 (-17.0351, 20.05) -> (-17.0351, 5.05)
  line L30 (-11.0351, 15.05) -> (-17.0351, 20.05)
  line L31 (-11.0351, 74.9) -> (-5.0851, 74.9)
  line L32 (-5.0851, 60) -> (-5.0851, 74.9)
  line L33 (-11.0351, 64.9735) -> (-10.9851, 64.9735)
  line L34 (-10.9851, 64.9735) -> (-5.0851, 60)
  line L35 (-11.0351, 64.95) -> (-11.0351, 74.95)
  line L36 (-17.0351, 74.95) -> (-11.0351, 74.95)
  line L37 (-17.0351, 59.95) -> (-17.0351, 74.95)
  line L38 (-11.0351, 64.95) -> (-17.0351, 59.95)
  point P17 (-100.8937, 64.9735)
  point P18 (-100.8937, 74.9)
  point P10 (-100.8937, 74.95)
  point P24 (-100.8937, 5.05)
  point P11 (-100.8937, 64.95)
  point P25 (-100.8937, 15.05)
  point P12 (-94.8937, 74.95)
  point P26 (-94.8937, 5.05)
  point P13 (-94.8937, 59.95)
  point P27 (-94.8937, 20.05)
  point P14 (-100.9437, 64.9735)
  point P22 (-100.9437, 15.0265)
  point P15 (-106.8437, 60)
  point P21 (-106.8437, 20)
  point P16 (-106.8437, 74.9)
  point P19 (-106.8437, 5.1)
  point P23 (-100.8937, 15.0265)
  point P20 (-100.8937, 5.1)
  point P42 (-11.0351, 74.95)
  point P43 (-11.0351, 64.95)
  point P44 (-17.0351, 74.95)
  point P45 (-17.0351, 59.95)
  point P40 (-10.9851, 64.9735)
  point P39 (-5.0851, 60)
  point P37 (-5.0851, 74.9)
  point P41 (-11.0351, 64.9735)
  point P38 (-11.0351, 74.9)
  point P28 (-5.0851, 5.1)
  point P29 (-11.0351, 5.1)
  point P30 (-5.0851, 20)
  point P31 (-10.9851, 15.0265)
  point P32 (-11.0351, 15.0265)
  point P33 (-11.0351, 5.05)
  point P34 (-11.0351, 15.05)
  point P35 (-17.0351, 5.05)
  point P36 (-17.0351, 20.05)
  vertical L5
  horizontal L6
  midpoint L3 L5
  midpoint L2 L6
  coincident L7 P17
  coincident L4 P17
  perpendicular L7 L14
  coincident L4 P18
  symmetric L6 P10 P24
  symmetric L6 P11 P25
  symmetric L6 P12 P26
  symmetric L6 P13 P27
  symmetric L6 P14 P22
  symmetric L6 P15 P21
  symmetric L6 P16 P19
  symmetric L6 P17 P23
  symmetric L6 P18 P20
  symmetric L5 P10 P42
  symmetric L5 P11 P43
  symmetric L5 P12 P44
  symmetric L5 P13 P45
  symmetric L5 P14 P40
  symmetric L5 P15 P39
  symmetric L5 P16 P37
  symmetric L5 P17 P41
  symmetric L5 P18 P38
  symmetric L5 P19 P28
  symmetric L5 P20 P29
  symmetric L5 P21 P30
  symmetric L5 P22 P31
  symmetric L5 P23 P32
  symmetric L5 P24 P33
  symmetric L5 P25 P34
  symmetric L5 P26 P35
  symmetric L5 P27 P36
  dimension "d332_3_1_1" distance P12 P13 = 15 (= "join_width2")
  dimension "d333_3_1_1" distance P10 P12 = 6 (= "join_depth * 2")
  dimension "d334_3_1_1" distance P10 P11 = 10 (= "join_width1")
  dimension "d336_3_1_1" distance P15 P16 = 14.9 (= "join_width2 - ( 2 * wall_clearance )")
  dimension "d337_3_1_1" distance P16 P18 = 5.95 (= "join_depth * 2 - wall_clearance")
  dimension "d338_3_1_1" distance P14 P17 = 0.05 (= "wall_clearance")
position "Position28"
extrude "Extrude3" add sketch "Sketch3" profile of L1 L3 L4 L7 L8 L9 L10 L12 L11 L13 L14 L15 L16 L17 L18 L19 L20 L21 L22 against normal blind 0.95 named "d343_1_1" (magnitude of "-side_wall_thick1")
sketch "Sketch4" plane through (0, 61.9879, 0) normal (0, 1, 0) x axis (1, 0, 0)
  line L1 (11.0351, -5.05) -> (100.8937, -5.05)
  line L2 (11.0351, -74.95) -> (11.0351, -5.05)
  line L3 (100.8937, -74.95) -> (11.0351, -74.95)
  line L4 (100.8937, -5.05) -> (100.8937, -74.95)
  line L5 (36.6374, -5.05) -> (36.6374, -12.415)
  line L6 (26.6374, -5.05) -> (26.6374, -12.415)
  circle C1 centre (15.9644, -20) radius 1.7
  circle C2 centre (95.9644, -60) radius 1.7
  circle C3 centre (95.9644, -20) radius 1.7
  circle C4 centre (15.9644, -60) radius 1.7
  arc A1 centre (31.6374, -12.415) radius 5 clockwise from (36.6374, -12.415) to (26.6374, -12.415)
  point P12 (36.6374, -5.05)
  point P14 (26.6374, -5.05)
  coincident L1 P12
  tangent L5 A1
  coincident L1 P14
  tangent L6 A1
  perpendicular L1 L6
  dimension "cable_hole_d_1_1" diameter A1 = 10
position "Position29"
sketch "Sketch1" plane through (0, 0, 5) normal (0, 0, 1) x axis (-1, 0, 0)
  line L1 (-98.9644, -53.9879) -> (-98.9644, -59.9879)
  line L2 (-92.9644, -53.9879) -> (-98.9644, -53.9879)
  line L3 (-92.9644, -59.9879) -> (-92.9644, -53.9879)
  line L4 (-98.9644, -59.9879) -> (-92.9644, -59.9879)
  line L5 (-12.9644, 60.0121) -> (-12.9644, 66.0121)
  line L6 (-18.9644, 60.0121) -> (-12.9644, 60.0121)
  line L7 (-18.9644, 66.0121) -> (-18.9644, 60.0121)
  line L8 (-12.9644, 66.0121) -> (-18.9644, 66.0121)
  line L9 (-45.9644, -51.9879) -> (-20.9644, -51.9879)
  line L10 (-40.9644, -54.9879) -> (-45.9644, -51.9879)
  line L11 (-70.9644, -54.9879) -> (-40.9644, -54.9879)
  line L12 (-65.9644, -51.9879) -> (-70.9644, -54.9879)
  line L13 (-90.9644, -51.9879) -> (-65.9644, -51.9879)
  line L14 (-90.9644, -6.9879) -> (-90.9644, -51.9879)
  line L15 (-93.9644, -11.9879) -> (-90.9644, -6.9879)
  line L16 (-93.9644, 18.0121) -> (-93.9644, -11.9879)
  line L17 (-90.9644, 13.0121) -> (-93.9644, 18.0121)
  line L18 (-90.9644, 58.0121) -> (-90.9644, 13.0121)
  line L19 (-65.9644, 58.0121) -> (-90.9644, 58.0121)
  line L20 (-70.9644, 61.0121) -> (-65.9644, 58.0121)
  line L21 (-40.9644, 61.0121) -> (-70.9644, 61.0121)
  line L22 (-45.9644, 58.0121) -> (-40.9644, 61.0121)
  line L23 (-20.9644, 58.0121) -> (-45.9644, 58.0121)
  line L24 (-20.9644, 13.0121) -> (-20.9644, 58.0121)
  line L25 (-17.9644, 18.0121) -> (-20.9644, 13.0121)
  line L26 (-17.9644, -11.9879) -> (-17.9644, 18.0121)
  line L27 (-20.9644, -6.9879) -> (-17.9644, -11.9879)
  line L28 (-20.9644, -51.9879) -> (-20.9644, -6.9879)
  line L29 (-12.9644, -53.9879) -> (-18.9644, -53.9879)
  line L30 (-12.9644, -59.9879) -> (-12.9644, -53.9879)
  line L31 (-18.9644, -59.9879) -> (-12.9644, -59.9879)
  line L32 (-18.9644, -53.9879) -> (-18.9644, -59.9879)
  line L33 (-98.9644, 60.0121) -> (-92.9644, 60.0121)
  line L34 (-98.9644, 66.0121) -> (-98.9644, 60.0121)
  line L35 (-92.9644, 66.0121) -> (-98.9644, 66.0121)
  line L36 (-92.9644, 60.0121) -> (-92.9644, 66.0121)
  line L37 (-10.9644, -6.9879) -> (-10.9644, -61.9879)
  line L38 (-13.9644, -11.9879) -> (-10.9644, -6.9879)
  line L39 (-13.9644, 18.0121) -> (-13.9644, -11.9879)
  line L40 (-10.9644, 13.0121) -> (-13.9644, 18.0121)
  line L41 (-10.9644, 68.0121) -> (-10.9644, 13.0121)
  line L42 (-45.9644, 68.0121) -> (-10.9644, 68.0121)
  line L43 (-40.9644, 65.0121) -> (-45.9644, 68.0121)
  line L44 (-70.9644, 65.0121) -> (-40.9644, 65.0121)
  line L45 (-65.9644, 68.0121) -> (-70.9644, 65.0121)
  line L46 (-100.9644, 68.0121) -> (-65.9644, 68.0121)
  line L47 (-100.9644, 13.0121) -> (-100.9644, 68.0121)
  line L48 (-97.9644, 18.0121) -> (-100.9644, 13.0121)
  line L49 (-97.9644, -11.9879) -> (-97.9644, 18.0121)
  line L50 (-100.9644, -6.9879) -> (-97.9644, -11.9879)
  line L51 (-100.9644, -61.9879) -> (-100.9644, -6.9879)
  line L52 (-65.9644, -61.9879) -> (-100.9644, -61.9879)
  line L53 (-70.9644, -58.9879) -> (-65.9644, -61.9879)
  line L54 (-40.9644, -58.9879) -> (-70.9644, -58.9879)
  line L55 (-45.9644, -61.9879) -> (-40.9644, -58.9879)
  line L56 (-10.9644, -61.9879) -> (-45.9644, -61.9879)
  line L57 (-100.9644, -61.9879) -> (-10.9644, -61.9879)
  line L58 (-99.9644, -60.9879) -> (-100.9644, -61.9879)
  line L59 (-91.9644, -60.9879) -> (-99.9644, -60.9879)
  line L60 (-91.9644, -59.9879) -> (-91.9644, -60.9879)
  line L61 (-19.9644, -59.9879) -> (-91.9644, -59.9879)
  line L62 (-19.9644, -60.9879) -> (-19.9644, -59.9879)
  line L63 (-11.9644, -60.9879) -> (-19.9644, -60.9879)
  line L64 (-10.9644, -61.9879) -> (-11.9644, -60.9879)
  line L65 (-99.9437, -61.0379) -> (-100.8937, -61.9879)
  line L66 (-91.9144, -61.0379) -> (-99.9437, -61.0379)
  line L67 (-91.9144, -60.0379) -> (-91.9144, -61.0379)
  line L68 (-20.0144, -60.0379) -> (-91.9144, -60.0379)
  line L69 (-20.0144, -61.0379) -> (-20.0144, -60.0379)
  line L70 (-11.9851, -61.0379) -> (-20.0144, -61.0379)
  line L71 (-11.0351, -61.9879) -> (-11.9851, -61.0379)
  circle C1 centre (-24.4644, 61.5121) radius 1.7
  circle C2 centre (-93.9644, 54.5121) radius 1.7
  circle C3 centre (-87.4644, -55.4879) radius 1.7
  circle C4 centre (-17.4644, -48.4879) radius 1.7
  circle C5 centre (-24.4644, -55.4879) radius 1.7
  circle C6 centre (-93.9644, -48.4879) radius 1.7
  circle C7 centre (-87.4644, 61.5121) radius 1.7
  circle C8 centre (-17.4644, 54.5121) radius 1.7
  point P46 (-10.9644, -61.9879)
  point P74 (-10.9644, -61.9879)
  point P61 (-100.9644, -61.9879)
  point P76 (-100.9644, -61.9879)
  point P68 (-99.9644, -60.9879)
  point P77 (-99.9644, -60.9879)
  point P69 (-91.9644, -60.9879)
  point P78 (-91.9644, -60.9879)
  point P70 (-91.9644, -59.9879)
  point P79 (-91.9644, -59.9879)
  point P71 (-19.9644, -59.9879)
  point P80 (-19.9644, -59.9879)
  point P72 (-19.9644, -60.9879)
  point P81 (-19.9644, -60.9879)
  point P73 (-11.9644, -60.9879)
  point P82 (-11.9644, -60.9879)
  point P89 (-11.0351, -61.9879)
  point P90 (-100.8937, -61.9879)
  point P75 (-100.9644, -61.9879)
  coincident P46 P74
  coincident P61 P76
  coincident P68 P77
  coincident P69 P78
  coincident P70 P79
  coincident P71 P80
  coincident P72 P81
  coincident P73 P82
  coincident L56 P89
  coincident L52 P90
  dimension "d228_3_2_2" distance L57 L70 = 0.95 (= "side_wall_thick1_2")
  dimension "d229_3_2_2" distance L57 L68 = 1.95 (= "side_wall_thick2_2")
  dimension "d230_3_2_2" distance L57 L66 = 0.95 (= "side_wall_thick1_2")
  dimension "d231_3_2_2" distance P74 P75 = 90 (= "plate_height_2")
  dimension "d232_3_2_2" distance L64 L71 = 0.05 (= "wall_clearance_2")
  dimension "d233_3_2_2" distance L58 L65 = 0.05 (= "wall_clearance_2")
  dimension "d234_3_2_2" angle L57 L58 = 45 (= "wall_rorner_angle_5")
  dimension "d235_3_2_2" distance P74 L69 = 9.05 (= "side_wall_col_length_2")
  dimension "d244_3_2_2" distance P75 L67 = 9.05 (= "side_wall_col_length_2")
extrude "Extrude1" new body sketch "Sketch1" profile of L52 L53 L55 L56 blind 69.9 (= "column_height_2 - ( 2 * wall_clearance_2 )") named "d217_3_2_2" from offset 0.05 (= "wall_clearance_2") named "d216_3_2_2"
sketch "Sketch2" plane through (0, 61.9879, 0) normal (0, 1, 0) x axis (-1, 0, 0)
  line L1 (-11.0351, 74.95) -> (-100.8937, 74.95)
  line L2 (-100.8937, 74.95) -> (-100.8937, 5.05)
  line L3 (-11.0351, 74.95) -> (-11.0351, 5.05)
  line L4 (-11.0351, 5.05) -> (-100.8937, 5.05)
  line L5 (-11.0351, 74.95) -> (-11.0351, 5.05)
  line L6 (-100.8937, 74.95) -> (-11.0351, 74.95)
  line L7 (-100.8937, 5.05) -> (-100.8937, 74.95)
  line L8 (-90.8937, 64.95) -> (-21.0351, 64.95)
  line L9 (-90.8937, 15.05) -> (-90.8937, 64.95)
  line L10 (-21.0351, 15.05) -> (-90.8937, 15.05)
  line L11 (-21.0351, 64.95) -> (-21.0351, 15.05)
  circle C1 centre (-95.9644, 60) radius 1.7
  circle C2 centre (-95.9644, 20) radius 1.7
  circle C3 centre (-15.9644, 20) radius 1.7
  circle C4 centre (-15.9644, 60) radius 1.7
  dimension "d227_3_2_2" = -10 (= "-plate_square_thick_2")
hole "Hole1" HoleDepth 4 named "d220_3_2_2" HoleDiameter 3.4 named "d221_3_2_2" TipAngle 118 named "d222_3_2_2"
sketch "Sketch3" plane through (0, 61.9879, 0) normal (0, 1, 0) x axis (-1, 0, 0)
  line L1 (-11.0351, 5.05) -> (-100.8937, 5.05)
  line L2 (-11.0351, 74.95) -> (-11.0351, 5.05)
  line L3 (-100.8937, 74.95) -> (-11.0351, 74.95)
  line L4 (-100.8937, 5.05) -> (-100.8937, 74.95)
  line L5 (-55.9644, -6.6527) -> (-55.9644, 156.5527)
  line L6 (83.5909, 40) -> (-105.6612, 40)
  line L7 (-100.8937, 64.95) -> (-100.8937, 74.95)
  line L8 (-94.8937, 74.95) -> (-100.8937, 74.95)
  line L9 (-94.8937, 59.95) -> (-94.8937, 74.95)
  line L10 (-100.8937, 64.95) -> (-94.8937, 59.95)
  line L11 (-100.9437, 64.9735) -> (-106.8437, 60)
  line L12 (-106.8437, 60) -> (-106.8437, 74.9)
  line L13 (-100.8937, 64.9735) -> (-100.9437, 64.9735)
  line L14 (-100.8937, 74.9) -> (-106.8437, 74.9)
  line L15 (-100.8937, 5.1) -> (-106.8437, 5.1)
  line L16 (-106.8437, 20) -> (-106.8437, 5.1)
  line L17 (-100.9437, 15.0265) -> (-106.8437, 20)
  line L18 (-100.8937, 15.0265) -> (-100.9437, 15.0265)
  line L19 (-100.8937, 15.05) -> (-100.8937, 5.05)
  line L20 (-94.8937, 5.05) -> (-100.8937, 5.05)
  line L21 (-94.8937, 20.05) -> (-94.8937, 5.05)
  line L22 (-100.8937, 15.05) -> (-94.8937, 20.05)
  line L23 (-11.0351, 5.1) -> (-5.0851, 5.1)
  line L24 (-5.0851, 20) -> (-5.0851, 5.1)
  line L25 (-10.9851, 15.0265) -> (-5.0851, 20)
  line L26 (-11.0351, 15.0265) -> (-10.9851, 15.0265)
  line L27 (-11.0351, 15.05) -> (-11.0351, 5.05)
  line L28 (-17.0351, 5.05) -> (-11.0351, 5.05)
  line L29 (-17.0351, 20.05) -> (-17.0351, 5.05)
  line L30 (-11.0351, 15.05) -> (-17.0351, 20.05)
  line L31 (-11.0351, 74.9) -> (-5.0851, 74.9)
  line L32 (-5.0851, 60) -> (-5.0851, 74.9)
  line L33 (-11.0351, 64.9735) -> (-10.9851, 64.9735)
  line L34 (-10.9851, 64.9735) -> (-5.0851, 60)
  line L35 (-11.0351, 64.95) -> (-11.0351, 74.95)
  line L36 (-17.0351, 74.95) -> (-11.0351, 74.95)
  line L37 (-17.0351, 59.95) -> (-17.0351, 74.95)
  line L38 (-11.0351, 64.95) -> (-17.0351, 59.95)
  point P17 (-100.8937, 64.9735)
  point P18 (-100.8937, 74.9)
  point P10 (-100.8937, 74.95)
  point P24 (-100.8937, 5.05)
  point P11 (-100.8937, 64.95)
  point P25 (-100.8937, 15.05)
  point P12 (-94.8937, 74.95)
  point P26 (-94.8937, 5.05)
  point P13 (-94.8937, 59.95)
  point P27 (-94.8937, 20.05)
  point P14 (-100.9437, 64.9735)
  point P22 (-100.9437, 15.0265)
  point P15 (-106.8437, 60)
  point P21 (-106.8437, 20)
  point P16 (-106.8437, 74.9)
  point P19 (-106.8437, 5.1)
  point P23 (-100.8937, 15.0265)
  point P20 (-100.8937, 5.1)
  point P42 (-11.0351, 74.95)
  point P43 (-11.0351, 64.95)
  point P44 (-17.0351, 74.95)
  point P45 (-17.0351, 59.95)
  point P40 (-10.9851, 64.9735)
  point P39 (-5.0851, 60)
  point P37 (-5.0851, 74.9)
  point P41 (-11.0351, 64.9735)
  point P38 (-11.0351, 74.9)
  point P28 (-5.0851, 5.1)
  point P29 (-11.0351, 5.1)
  point P30 (-5.0851, 20)
  point P31 (-10.9851, 15.0265)
  point P32 (-11.0351, 15.0265)
  point P33 (-11.0351, 5.05)
  point P34 (-11.0351, 15.05)
  point P35 (-17.0351, 5.05)
  point P36 (-17.0351, 20.05)
  vertical L5
  horizontal L6
  midpoint L3 L5
  midpoint L2 L6
  coincident L7 P17
  coincident L4 P17
  perpendicular L7 L14
  coincident L4 P18
  symmetric L6 P10 P24
  symmetric L6 P11 P25
  symmetric L6 P12 P26
  symmetric L6 P13 P27
  symmetric L6 P14 P22
  symmetric L6 P15 P21
  symmetric L6 P16 P19
  symmetric L6 P17 P23
  symmetric L6 P18 P20
  symmetric L5 P10 P42
  symmetric L5 P11 P43
  symmetric L5 P12 P44
  symmetric L5 P13 P45
  symmetric L5 P14 P40
  symmetric L5 P15 P39
  symmetric L5 P16 P37
  symmetric L5 P17 P41
  symmetric L5 P18 P38
  symmetric L5 P19 P28
  symmetric L5 P20 P29
  symmetric L5 P21 P30
  symmetric L5 P22 P31
  symmetric L5 P23 P32
  symmetric L5 P24 P33
  symmetric L5 P25 P34
  symmetric L5 P26 P35
  symmetric L5 P27 P36
  dimension "d332_3_2_2" distance P12 P13 = 15 (= "join_width2_2")
  dimension "d333_3_2_2" distance P10 P12 = 6 (= "join_depth_2 * 2")
  dimension "d334_3_2_2" distance P10 P11 = 10 (= "join_width1_2")
  dimension "d336_3_2_2" distance P15 P16 = 14.9 (= "join_width2_2 - ( 2 * wall_clearance_2 )")
  dimension "d337_3_2_2" distance P16 P18 = 5.95 (= "join_depth_2 * 2 - wall_clearance_2")
  dimension "d338_3_2_2" distance P14 P17 = 0.05 (= "wall_clearance_2")
position "Position30"
sketch "Sketch4" plane through (0, 61.9879, 0) normal (0, 1, 0) x axis (1, 0, 0)
  line L1 (11.0351, -5.05) -> (100.8937, -5.05)
  line L2 (11.0351, -74.95) -> (11.0351, -5.05)
  line L3 (100.8937, -74.95) -> (11.0351, -74.95)
  line L4 (100.8937, -5.05) -> (100.8937, -74.95)
  line L5 (45.9644, -5.05) -> (45.9644, -12.415)
  line L6 (35.9644, -5.05) -> (35.9644, -12.415)
  line L7 (65.9644, -5.05) -> (65.9644, -12.423)
  line L8 (75.967, -5.05) -> (75.9644, -12.4248)
  line L9 (55.9644, 6.6527) -> (55.9644, -156.5527)
  circle C1 centre (15.9644, -20) radius 1.7
  circle C2 centre (95.9644, -60) radius 1.7
  circle C3 centre (95.9644, -20) radius 1.7
  circle C4 centre (15.9644, -60) radius 1.7
  arc A1 centre (40.9644, -12.415) radius 5 clockwise from (45.9644, -12.415) to (35.9644, -12.415)
  arc A2 centre (70.9644, -12.423) radius 5 clockwise from (75.9644, -12.4248) to (65.9644, -12.423)
  point P12 (45.9644, -5.05)
  point P14 (35.9644, -5.05)
  coincident L1 P12
  tangent L5 A1
  coincident L1 P14
  tangent L6 A1
  perpendicular L1 L6
  tangent A2 L8
  tangent L7 A2
  dimension "cable_hole_d_2_2" diameter A1 = 10
  dimension "d534_2" diameter A2 = 10
  dimension "d535_2" distance L7 L9 = 10
  dimension "d536_2" distance L5 L9 = 10
extrude "Extrude4" cut sketch "Sketch4" profile of A1 L1 L5 L6 L7 A2 L8 against normal blind 2 named "d517_2_2"
position "Position31"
